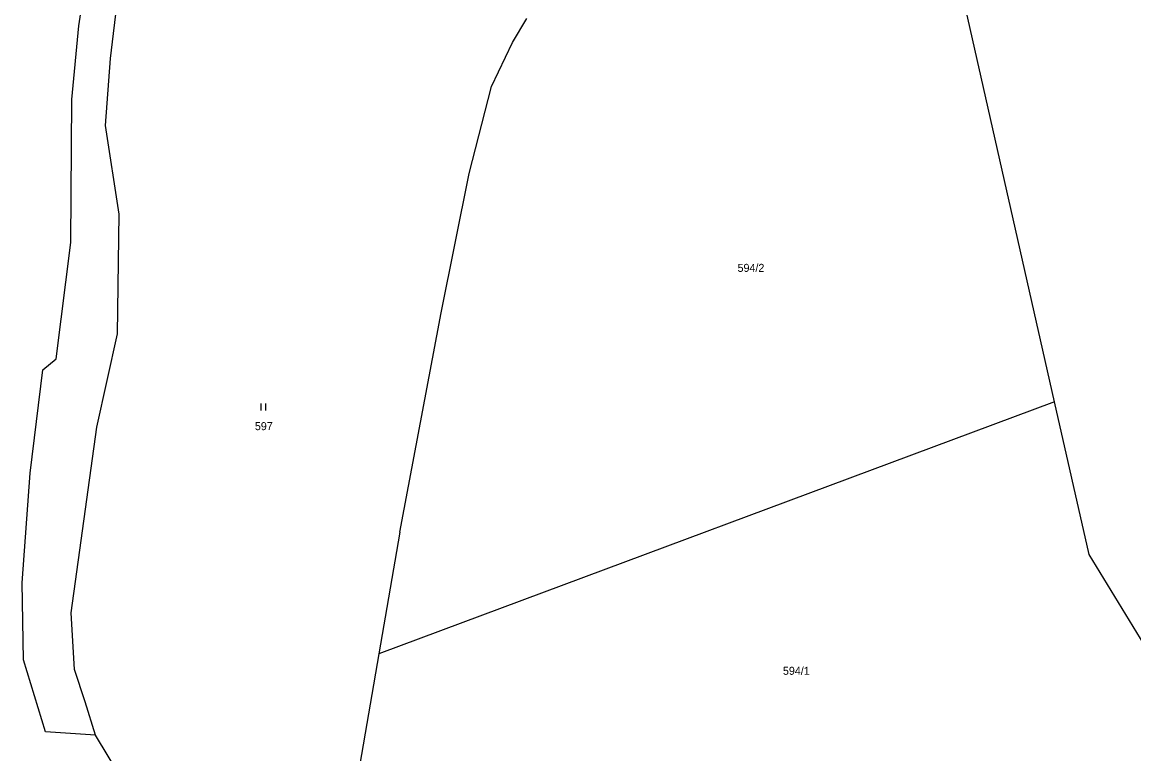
# Model space of a CAD drawing. Extents: x -653193 to -651624, y -1092017 to -1090260.
# Drawn here: x -653062.9 to -652826.7, y -1091598.3 to -1091442.9 of the extents above; entities that cross this region are included whole.
import ezdxf
from ezdxf.enums import TextEntityAlignment as Align

# ---------------------------------------------------------------- set-up
doc = ezdxf.new("R2010")
doc.units = 0
doc.header["$LTSCALE"] = 0.68
doc.layers.add('1', color=7, linetype='Continuous', lineweight=25)
doc.layers.add('3', color=7, linetype='Continuous', lineweight=25)
doc.layers.add('2', color=7, linetype='Continuous')

msp = doc.modelspace()

# ---------------------------------------------------------------- linework, layer by layer
at = {"layer": '1'}
for p, q in [((-652843.58, -1091523.54), (-652872.86, -1091394.17)), ((-653044.11, -1091450.65), (-653040.83, -1091423.38)), ((-653050.88, -1091443.73), (-653048.92, -1091431.03)), ((-652958.72, -1091447.26), (-652955.7, -1091442.14)), ((-653052.37, -1091459.34), (-653050.88, -1091443.73)), ((-652963.17, -1091456.59), (-652958.72, -1091447.26)), ((-653045.16, -1091464.85), (-653044.11, -1091450.65)), ((-652967.92, -1091475.03), (-652963.17, -1091456.59)), ((-653052.57, -1091489.7), (-653052.37, -1091459.34)), ((-653042.26, -1091483.71), (-653045.16, -1091464.85)), ((-652973.89, -1091504.68), (-652967.92, -1091475.03)), ((-653042.61, -1091509.1), (-653042.26, -1091483.71)), ((-653055.7, -1091514.42), (-653052.57, -1091489.7)), ((-652982.68, -1091551.23), (-652973.89, -1091504.68)), ((-653047.04, -1091528.97), (-653042.61, -1091509.1)), ((-653058.47, -1091516.78), (-653055.7, -1091514.42)), ((-653061.22, -1091538.69), (-653058.47, -1091516.78)), ((-652836.23, -1091556.01), (-652843.58, -1091523.54)), ((-653052.46, -1091568.39), (-653047.04, -1091528.97)), ((-653062.88, -1091562.03), (-653061.22, -1091538.69)), ((-652982.68, -1091551.23), (-652987.13, -1091577.09)), ((-652809.38, -1091599.93), (-652836.23, -1091556.01)), ((-653062.59, -1091578.33), (-653062.88, -1091562.03)), ((-653051.78, -1091580.42), (-653052.46, -1091568.39)), ((-653057.97, -1091593.62), (-653062.59, -1091578.33)), ((-653049.54, -1091587.25), (-653051.78, -1091580.42)), ((-653047.35, -1091594.38), (-653049.54, -1091587.25)), ((-653047.35, -1091594.38), (-653057.97, -1091593.62)), ((-653041.4, -1091604.11), (-653047.35, -1091594.38))]:
    msp.add_line(p, q, dxfattribs=at)
msp.add_lwpolyline([(-652843.58, -1091523.54), (-652987.13, -1091577.09), (-652993.35, -1091613.24)], dxfattribs=at)
at = {"layer": '3'}
for p, q in [((-653012.111, -1091525.42), (-653012.111, -1091523.92)), ((-653011.11, -1091525.42), (-653011.11, -1091523.92))]:
    msp.add_line(p, q, dxfattribs=at)

# ---------------------------------------------------------------- texts
at = {"layer": '2'}
for s, p in [('594/2', (-652908.07, -1091495.955)), ('597', (-653011.559, -1091529.575)), ('594/1', (-652898.43, -1091581.535))]:
    msp.add_text(s, height=1.7, dxfattribs=at).set_placement(p, align=Align.CENTER)

doc.saveas('drawing.dxf')
